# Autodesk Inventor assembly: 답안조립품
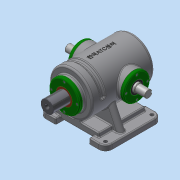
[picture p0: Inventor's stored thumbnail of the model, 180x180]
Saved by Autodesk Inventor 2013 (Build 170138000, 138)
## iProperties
Created: 2018-06
Part Number: 답안조립품
Document SubType Name: Assembly
Designer: Administrator
Mass: 8560.83 g
Surface Area: 4294.68 cm^2
Volume: 2307.11 cm^3
Density: 3.71063 g/cm^3
Author: Administrator
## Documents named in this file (13)
- C:\Users\Administrator\Desktop\380628V1006\답안조립품.iam
- C:\Users\Administrator\Desktop\380628V1006\본체.ipt
- C:\Users\Administrator\Desktop\380628V1006\가변스프링.ipt
- C:\Users\Administrator\Desktop\380628V1006\베어링 6205.ipt
- 베어링 6205.ipt
- C:\Users\Administrator\Desktop\380628V1006\볼트 M4.ipt
- C:\Users\Administrator\Desktop\380628V1006\부시.ipt
- C:\Users\Administrator\Desktop\380628V1006\슬라이드 커버.ipt
- C:\Users\Administrator\Desktop\380628V1006\슬라이드.ipt
- C:\Users\Administrator\Desktop\380628V1006\오일실.ipt
- 오일실.ipt
- C:\Users\Administrator\Desktop\380628V1006\축 커버.ipt
- C:\Users\Administrator\Desktop\380628V1006\편심축.ipt
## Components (1 placed, 1 different names)
1. 가변스프링:1
